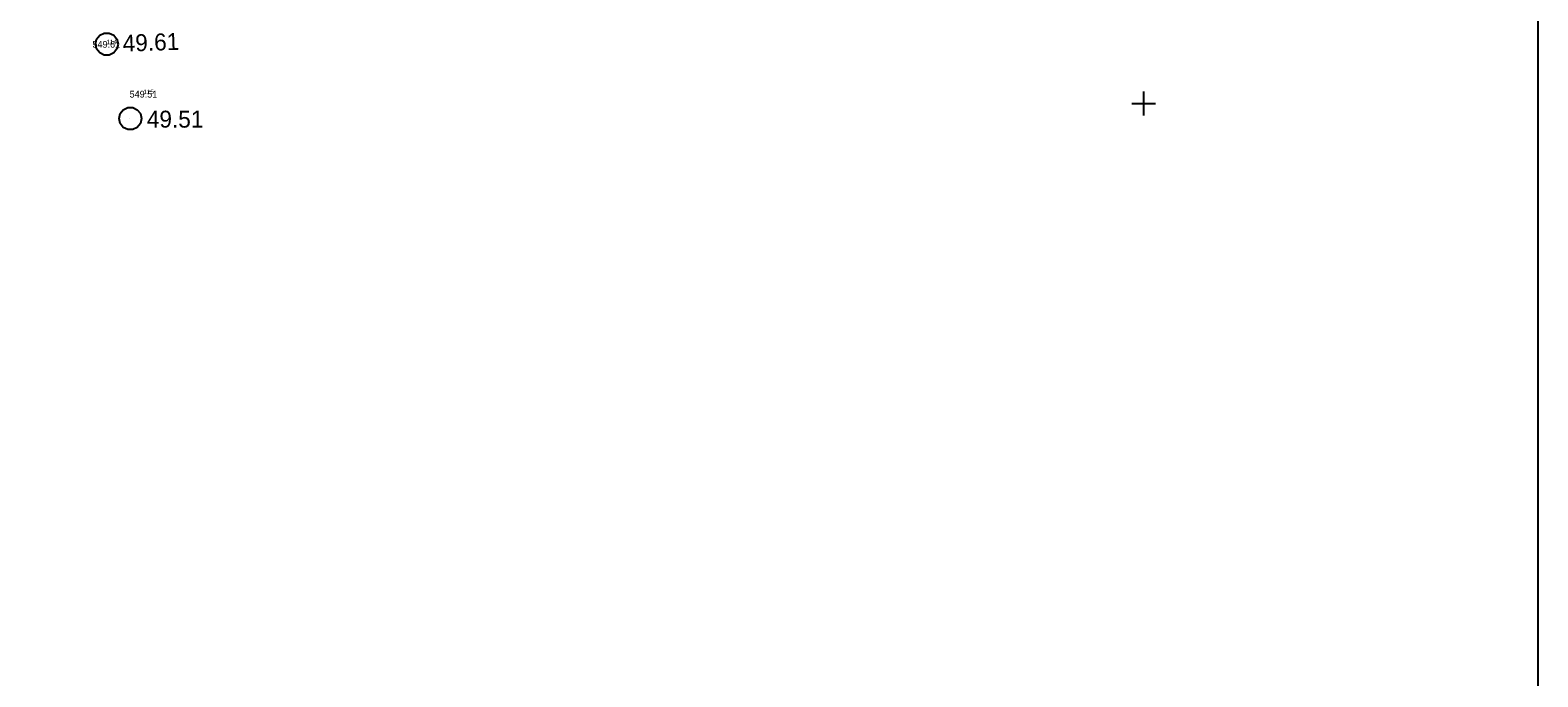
# Model space of a CAD drawing. Extents: x -866693 to -866303, y -1041966 to -1040244.
# Drawn here: x -866549.4 to -866482.5, y -1040325.4 to -1040296.8 of the extents above; entities that cross this region are included whole.
import ezdxf

# ---------------------------------------------------------------- set-up
doc = ezdxf.new("R2010")
doc.units = 0
for name, color, linetype in [('52 šachta bez rozlišení', 7, 'Continuous'), ('Bod', 7, 'Continuous'), ('Formát', 7, 'Continuous'), ('Nadmořská výška', 7, 'Continuous'), ('Nadmořská výška_tisk', 7, 'Continuous'), ('Síť křížek', 7, 'Continuous'), ('Číslo bodu', 7, 'Continuous')]:
    doc.layers.add(name, color=color, linetype=linetype)

msp = doc.modelspace()

# ---------------------------------------------------------------- linework, layer by layer
at = {"layer": '52 šachta bez rozlišení'}
for p, q in [((-866546.479, -1040297.367), (-866546.429, -1040297.15)), ((-866546.429, -1040297.15), (-866546.291, -1040296.976)), ((-866546.291, -1040296.976), (-866546.09, -1040296.879)), ((-866546.09, -1040296.879), (-866545.867, -1040296.879)), ((-866545.867, -1040296.879), (-866545.667, -1040296.976)), ((-866545.667, -1040296.976), (-866545.528, -1040297.15)), ((-866545.528, -1040297.15), (-866545.479, -1040297.367)), ((-866546.429, -1040297.584), (-866546.479, -1040297.367)), ((-866546.291, -1040297.758), (-866546.429, -1040297.584)), ((-866546.09, -1040297.854), (-866546.291, -1040297.758)), ((-866545.667, -1040297.758), (-866545.867, -1040297.854)), ((-866545.528, -1040297.584), (-866545.667, -1040297.758)), ((-866545.479, -1040297.367), (-866545.528, -1040297.584)), ((-866545.867, -1040297.854), (-866546.09, -1040297.854)), ((-866545.437, -1040300.669), (-866545.387, -1040300.452)), ((-866545.387, -1040300.452), (-866545.249, -1040300.278)), ((-866545.249, -1040300.278), (-866545.048, -1040300.181)), ((-866545.048, -1040300.181), (-866544.825, -1040300.181)), ((-866544.825, -1040300.181), (-866544.625, -1040300.278)), ((-866544.625, -1040300.278), (-866544.486, -1040300.452)), ((-866544.486, -1040300.452), (-866544.437, -1040300.669)), ((-866545.387, -1040300.886), (-866545.437, -1040300.669)), ((-866545.249, -1040301.06), (-866545.387, -1040300.886)), ((-866545.048, -1040301.156), (-866545.249, -1040301.06)), ((-866544.825, -1040301.156), (-866545.048, -1040301.156)), ((-866544.625, -1040301.06), (-866544.825, -1040301.156)), ((-866544.486, -1040300.886), (-866544.625, -1040301.06)), ((-866544.437, -1040300.669), (-866544.486, -1040300.886))]:
    msp.add_line(p, q, dxfattribs=at)
at = {"layer": 'Bod'}
for p, q in [((-866545.994, -1040297.379), (-866545.994, -1040297.379)), ((-866544.952, -1040300.681), (-866544.952, -1040300.681))]:
    msp.add_line(p, q, dxfattribs=at)
at = {"layer": 'Formát'}
msp.add_lwpolyline([(-866692.523, -1040244.107), (-866482.523, -1040244.107), (-866482.523, -1040541.107), (-866692.523, -1040541.107)], close=True, dxfattribs=at)
at = {"layer": 'Síť křížek'}
for p, q in [((-866500, -1040300.53), (-866500, -1040299.47)), ((-866500.53, -1040300), (-866499.47, -1040300))]:
    msp.add_line(p, q, dxfattribs=at)

# ---------------------------------------------------------------- texts
at = {"layer": 'Nadmořská výška'}
for s, p in [('549.61', (-866546.616, -1040297.53)), ('549.51', (-866544.968, -1040299.74))]:
    msp.add_text(s, height=0.3, dxfattribs=at).set_placement(p)
at = {"layer": 'Nadmořská výška_tisk'}
msp.add_text('49.61', height=0.75, rotation=1.99242, dxfattribs=at).set_placement((-866545.263, -1040297.709))
msp.add_text('49.51', height=0.75, dxfattribs=at).set_placement((-866544.205, -1040301.072))
at = {"layer": 'Číslo bodu'}
for s, p in [('114', (-866545.994, -1040297.379)), ('115', (-866544.351, -1040299.585))]:
    msp.add_text(s, height=0.2, dxfattribs=at).set_placement(p)

doc.saveas('drawing.dxf')
